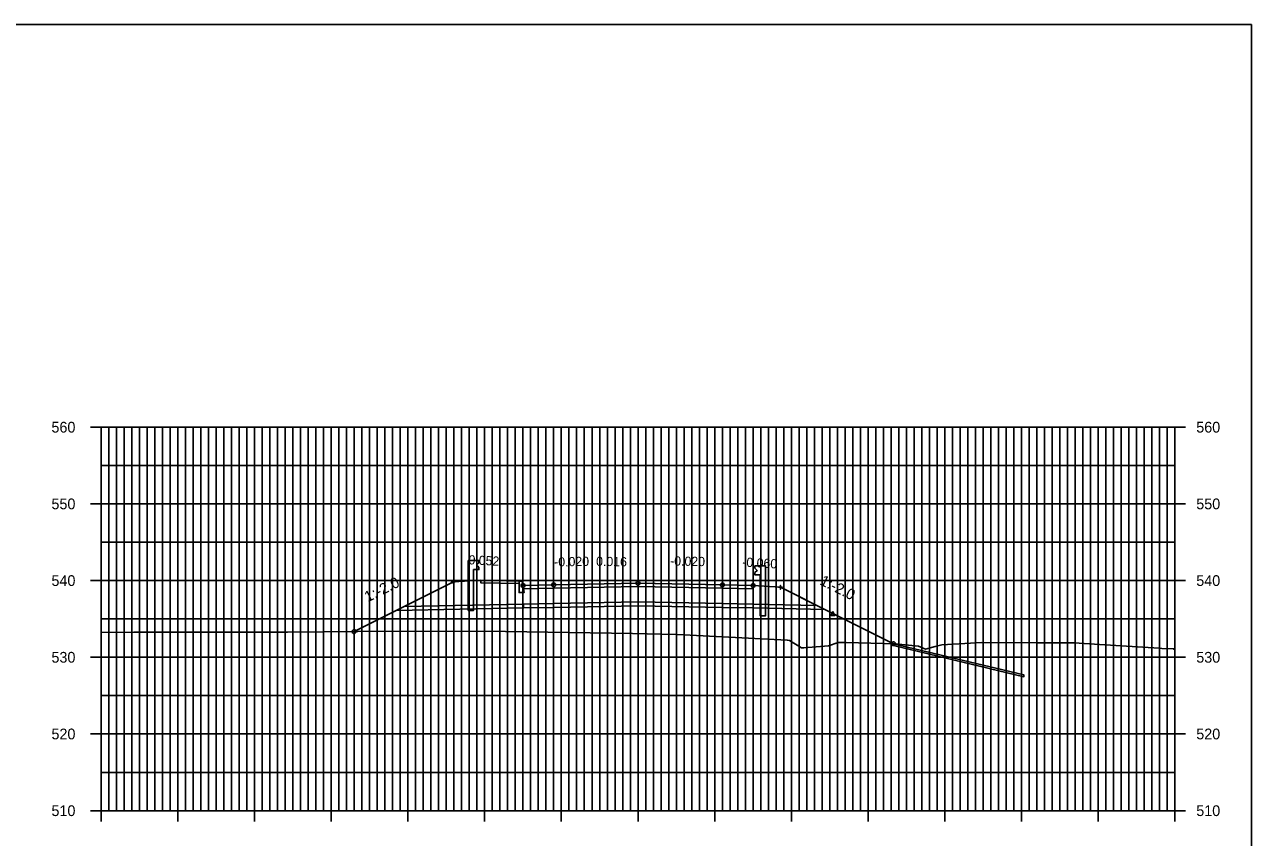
# Model space of a CAD drawing. Extents: x 1509063 to 1512863, y 401160 to 402918.
# Drawn here: x 1511622.7 to 1511782.7, y 402356.1 to 402462.1 of the extents above; entities that cross this region are included whole.
import ezdxf

# ---------------------------------------------------------------- set-up
doc = ezdxf.new("R2010")
doc.units = 0
for name, color, linetype in [('DD_P', 7, 'Continuous'), ('DDG_P', 7, 'Continuous'), ('LFILL_P', 7, 'Continuous'), ('NBL1', 7, 'Continuous'), ('PET_P', 7, 'Continuous'), ('PRC', 7, 'Continuous'), ('PSP_P', 7, 'Continuous'), ('RBS_P', 7, 'Continuous'), ('RCC_P', 7, 'Continuous'), ('RGR_P', 7, 'Continuous'), ('XAX_P', 7, 'Continuous'), ('XAXTIC_P', 7, 'Continuous'), ('XAXTXT_P_T', 7, 'Continuous'), ('XGL_P', 7, 'Continuous'), ('XSL1_P', 7, 'Continuous'), ('XSL1_P_T', 7, 'Continuous'), ('XSL2_P', 7, 'Continuous'), ('XSL3_P', 7, 'Continuous'), ('XSLOG', 7, 'Continuous')]:
    doc.layers.add(name, color=color, linetype=linetype)

msp = doc.modelspace()

# ---------------------------------------------------------------- linework, layer by layer
at = {"layer": 'DD_P'}
msp.add_lwpolyline([(1511728.15, 402385.55), (1511728.4, 402385.05), (1511727.9, 402385.05)], close=True, dxfattribs=at)
at = {"layer": 'DDG_P'}
msp.add_lwpolyline([(1511736.04, 402381.35), (1511753.05, 402377.29), (1511753.05, 402377.04), (1511736.04, 402381.1)], close=True, dxfattribs=at)
at = {"layer": 'LFILL_P'}
for points in [[(1511665.7, 402382.93), (1511678.65, 402389.41), (1511682.23, 402389.62)], [(1511717.73, 402388.93), (1511721.31, 402388.71), (1511728.15, 402385.3), (1511736.04, 402381.35)]]:
    msp.add_lwpolyline(points, dxfattribs=at)
for centre in [(1511665.7, 402382.93), (1511736.04, 402381.35)]:
    msp.add_circle(centre, 0.25, dxfattribs=at)
at = {"layer": 'NBL1'}
msp.add_lwpolyline([(1511782.73, 402252.08), (1511462.73, 402252.08), (1511462.73, 402462.08), (1511782.73, 402462.08)], close=True, dxfattribs=at)
at = {"layer": 'PET_P'}
for centre in [(1511691.73, 402389.01), (1511713.73, 402389.01)]:
    msp.add_circle(centre, 0.25, dxfattribs=at)
at = {"layer": 'PRC'}
msp.add_circle((1511702.73, 402389.23), 0.25, dxfattribs=at)
at = {"layer": 'PSP_P'}
for centre in [(1511687.73, 402388.93), (1511717.73, 402388.93)]:
    msp.add_circle(centre, 0.25, dxfattribs=at)
at = {"layer": 'RBS_P'}
for points in [[(1511687.8, 402388.51), (1511691.73, 402388.59), (1511702.73, 402388.81), (1511702.73, 402386.81), (1511691.73, 402386.59), (1511687.8, 402386.51), (1511672.24, 402386.2), (1511678.65, 402389.41), (1511682.23, 402389.62), (1511682.23, 402389.29), (1511687.23, 402389.19), (1511687.23, 402388.02), (1511687.88, 402388.02)], [(1511702.73, 402388.81), (1511702.73, 402386.81), (1511713.73, 402386.59), (1511717.73, 402386.51), (1511726.05, 402386.35), (1511721.31, 402388.71), (1511717.73, 402388.93), (1511717.73, 402388.51), (1511713.73, 402388.59)]]:
    msp.add_lwpolyline(points, close=True, dxfattribs=at)
for points in [[(1511678.65, 402389.41), (1511678.65, 402389.66), (1511678.65, 402389.41), (1511678.4, 402389.41), (1511678.65, 402389.41), (1511678.65, 402389.16), (1511678.65, 402389.41), (1511678.9, 402389.41)], [(1511721.31, 402388.71), (1511721.31, 402388.96), (1511721.31, 402388.71), (1511721.06, 402388.71), (1511721.31, 402388.71), (1511721.31, 402388.46), (1511721.31, 402388.71), (1511721.56, 402388.71)]]:
    msp.add_lwpolyline(points, dxfattribs=at)
at = {"layer": 'RCC_P'}
msp.add_lwpolyline([(1511687.73, 402388.93), (1511687.63, 402389.51), (1511687.23, 402389.52), (1511687.23, 402388.02), (1511687.88, 402388.02)], close=True, dxfattribs=at)
at = {"layer": 'RGR_P'}
for points in [[(1511681.29, 402391.02), (1511681.98, 402391.02), (1511681.98, 402391.32), (1511681.68, 402391.6), (1511681.98, 402391.89), (1511681.98, 402392.19), (1511680.6, 402392.19), (1511680.6, 402385.69), (1511681.29, 402385.69)], [(1511718.66, 402390.33), (1511717.98, 402390.33), (1511717.98, 402390.63), (1511718.28, 402390.91), (1511717.98, 402391.2), (1511717.98, 402391.5), (1511719.36, 402391.5), (1511719.36, 402385), (1511718.66, 402385)]]:
    msp.add_lwpolyline(points, close=True, dxfattribs=at)
at = {"layer": 'XAX_P'}
for p, q in [((1511632.73, 402359.58), (1511632.73, 402409.58)), ((1511702.73, 402359.58), (1511702.73, 402409.58)), ((1511772.73, 402359.58), (1511772.73, 402409.58)), ((1511632.73, 402359.58), (1511772.73, 402359.58))]:
    msp.add_line(p, q, dxfattribs=at)
at = {"layer": 'XAXTIC_P'}
for p, q in [((1511631.33, 402409.58), (1511634.13, 402409.58)), ((1511701.33, 402409.58), (1511704.13, 402409.58)), ((1511774.13, 402409.58), (1511771.33, 402409.58)), ((1511631.33, 402399.58), (1511634.13, 402399.58)), ((1511701.33, 402399.58), (1511704.13, 402399.58)), ((1511774.13, 402399.58), (1511771.33, 402399.58)), ((1511631.33, 402389.58), (1511634.13, 402389.58)), ((1511701.33, 402389.58), (1511704.13, 402389.58)), ((1511774.13, 402389.58), (1511771.33, 402389.58)), ((1511631.33, 402379.58), (1511634.13, 402379.58)), ((1511701.33, 402379.58), (1511704.13, 402379.58)), ((1511774.13, 402379.58), (1511771.33, 402379.58)), ((1511631.33, 402369.58), (1511634.13, 402369.58)), ((1511701.33, 402369.58), (1511704.13, 402369.58)), ((1511774.13, 402369.58), (1511771.33, 402369.58)), ((1511632.73, 402358.18), (1511632.73, 402360.98)), ((1511642.73, 402358.18), (1511642.73, 402360.98)), ((1511652.73, 402358.18), (1511652.73, 402360.98)), ((1511662.73, 402358.18), (1511662.73, 402360.98)), ((1511672.73, 402358.18), (1511672.73, 402360.98)), ((1511682.73, 402358.18), (1511682.73, 402360.98)), ((1511692.73, 402358.18), (1511692.73, 402360.98)), ((1511702.73, 402358.18), (1511702.73, 402360.98)), ((1511712.73, 402358.18), (1511712.73, 402360.98)), ((1511722.73, 402358.18), (1511722.73, 402360.98)), ((1511732.73, 402358.18), (1511732.73, 402360.98)), ((1511742.73, 402358.18), (1511742.73, 402360.98)), ((1511752.73, 402358.18), (1511752.73, 402360.98)), ((1511762.73, 402358.18), (1511762.73, 402360.98)), ((1511772.73, 402358.18), (1511772.73, 402360.98)), ((1511631.33, 402359.58), (1511634.13, 402359.58)), ((1511701.33, 402359.58), (1511704.13, 402359.58)), ((1511774.13, 402359.58), (1511771.33, 402359.58))]:
    msp.add_line(p, q, dxfattribs=at)
at = {"layer": 'XGL_P'}
for p, q in [((1511632.73, 402409.58), (1511772.73, 402409.58)), ((1511632.73, 402359.58), (1511632.73, 402409.58)), ((1511633.73, 402359.58), (1511633.73, 402409.58)), ((1511634.73, 402359.58), (1511634.73, 402409.58)), ((1511635.73, 402359.58), (1511635.73, 402409.58)), ((1511636.73, 402359.58), (1511636.73, 402409.58)), ((1511637.73, 402359.58), (1511637.73, 402409.58)), ((1511638.73, 402359.58), (1511638.73, 402409.58)), ((1511639.73, 402359.58), (1511639.73, 402409.58)), ((1511640.73, 402359.58), (1511640.73, 402409.58)), ((1511641.73, 402359.58), (1511641.73, 402409.58)), ((1511642.73, 402359.58), (1511642.73, 402409.58)), ((1511643.73, 402359.58), (1511643.73, 402409.58)), ((1511644.73, 402359.58), (1511644.73, 402409.58)), ((1511645.73, 402359.58), (1511645.73, 402409.58)), ((1511646.73, 402359.58), (1511646.73, 402409.58)), ((1511647.73, 402359.58), (1511647.73, 402409.58)), ((1511648.73, 402359.58), (1511648.73, 402409.58)), ((1511649.73, 402359.58), (1511649.73, 402409.58)), ((1511650.73, 402359.58), (1511650.73, 402409.58)), ((1511651.73, 402359.58), (1511651.73, 402409.58)), ((1511652.73, 402359.58), (1511652.73, 402409.58)), ((1511653.73, 402359.58), (1511653.73, 402409.58)), ((1511654.73, 402359.58), (1511654.73, 402409.58)), ((1511655.73, 402359.58), (1511655.73, 402409.58)), ((1511656.73, 402359.58), (1511656.73, 402409.58)), ((1511657.73, 402359.58), (1511657.73, 402409.58)), ((1511658.73, 402359.58), (1511658.73, 402409.58)), ((1511659.73, 402359.58), (1511659.73, 402409.58)), ((1511660.73, 402359.58), (1511660.73, 402409.58)), ((1511661.73, 402359.58), (1511661.73, 402409.58)), ((1511662.73, 402359.58), (1511662.73, 402409.58)), ((1511663.73, 402359.58), (1511663.73, 402409.58)), ((1511664.73, 402359.58), (1511664.73, 402409.58)), ((1511665.73, 402359.58), (1511665.73, 402409.58)), ((1511666.73, 402359.58), (1511666.73, 402409.58)), ((1511667.73, 402359.58), (1511667.73, 402409.58)), ((1511668.73, 402359.58), (1511668.73, 402409.58)), ((1511669.73, 402359.58), (1511669.73, 402409.58)), ((1511670.73, 402359.58), (1511670.73, 402409.58)), ((1511671.73, 402359.58), (1511671.73, 402409.58)), ((1511672.73, 402359.58), (1511672.73, 402409.58)), ((1511673.73, 402359.58), (1511673.73, 402409.58)), ((1511674.73, 402359.58), (1511674.73, 402409.58)), ((1511675.73, 402359.58), (1511675.73, 402409.58)), ((1511676.73, 402359.58), (1511676.73, 402409.58)), ((1511677.73, 402359.58), (1511677.73, 402409.58)), ((1511678.73, 402359.58), (1511678.73, 402409.58)), ((1511679.73, 402359.58), (1511679.73, 402409.58)), ((1511680.73, 402359.58), (1511680.73, 402409.58)), ((1511681.73, 402359.58), (1511681.73, 402409.58)), ((1511682.73, 402359.58), (1511682.73, 402409.58)), ((1511683.73, 402359.58), (1511683.73, 402409.58)), ((1511684.73, 402359.58), (1511684.73, 402409.58)), ((1511685.73, 402359.58), (1511685.73, 402409.58)), ((1511686.73, 402359.58), (1511686.73, 402409.58)), ((1511687.73, 402359.58), (1511687.73, 402409.58)), ((1511688.73, 402359.58), (1511688.73, 402409.58)), ((1511689.73, 402359.58), (1511689.73, 402409.58)), ((1511690.73, 402359.58), (1511690.73, 402409.58)), ((1511691.73, 402359.58), (1511691.73, 402409.58)), ((1511692.73, 402359.58), (1511692.73, 402409.58)), ((1511693.73, 402359.58), (1511693.73, 402409.58)), ((1511694.73, 402359.58), (1511694.73, 402409.58)), ((1511695.73, 402359.58), (1511695.73, 402409.58)), ((1511696.73, 402359.58), (1511696.73, 402409.58)), ((1511697.73, 402359.58), (1511697.73, 402409.58)), ((1511698.73, 402359.58), (1511698.73, 402409.58)), ((1511699.73, 402359.58), (1511699.73, 402409.58)), ((1511700.73, 402359.58), (1511700.73, 402409.58)), ((1511701.73, 402359.58), (1511701.73, 402409.58)), ((1511702.73, 402359.58), (1511702.73, 402409.58)), ((1511703.73, 402359.58), (1511703.73, 402409.58)), ((1511704.73, 402359.58), (1511704.73, 402409.58)), ((1511705.73, 402359.58), (1511705.73, 402409.58)), ((1511706.73, 402359.58), (1511706.73, 402409.58)), ((1511707.73, 402359.58), (1511707.73, 402409.58)), ((1511708.73, 402359.58), (1511708.73, 402409.58)), ((1511709.73, 402359.58), (1511709.73, 402409.58)), ((1511710.73, 402359.58), (1511710.73, 402409.58)), ((1511711.73, 402359.58), (1511711.73, 402409.58)), ((1511712.73, 402359.58), (1511712.73, 402409.58)), ((1511713.73, 402359.58), (1511713.73, 402409.58)), ((1511714.73, 402359.58), (1511714.73, 402409.58)), ((1511715.73, 402359.58), (1511715.73, 402409.58)), ((1511716.73, 402359.58), (1511716.73, 402409.58)), ((1511717.73, 402359.58), (1511717.73, 402409.58)), ((1511718.73, 402359.58), (1511718.73, 402409.58)), ((1511719.73, 402359.58), (1511719.73, 402409.58)), ((1511720.73, 402359.58), (1511720.73, 402409.58)), ((1511721.73, 402359.58), (1511721.73, 402409.58)), ((1511722.73, 402359.58), (1511722.73, 402409.58)), ((1511723.73, 402359.58), (1511723.73, 402409.58)), ((1511724.73, 402359.58), (1511724.73, 402409.58)), ((1511725.73, 402359.58), (1511725.73, 402409.58)), ((1511726.73, 402359.58), (1511726.73, 402409.58)), ((1511727.73, 402359.58), (1511727.73, 402409.58)), ((1511728.73, 402359.58), (1511728.73, 402409.58)), ((1511729.73, 402359.58), (1511729.73, 402409.58)), ((1511730.73, 402359.58), (1511730.73, 402409.58)), ((1511731.73, 402359.58), (1511731.73, 402409.58)), ((1511732.73, 402359.58), (1511732.73, 402409.58)), ((1511733.73, 402359.58), (1511733.73, 402409.58)), ((1511734.73, 402359.58), (1511734.73, 402409.58)), ((1511735.73, 402359.58), (1511735.73, 402409.58)), ((1511736.73, 402359.58), (1511736.73, 402409.58)), ((1511737.73, 402359.58), (1511737.73, 402409.58)), ((1511738.73, 402359.58), (1511738.73, 402409.58)), ((1511739.73, 402359.58), (1511739.73, 402409.58)), ((1511740.73, 402359.58), (1511740.73, 402409.58)), ((1511741.73, 402359.58), (1511741.73, 402409.58)), ((1511742.73, 402359.58), (1511742.73, 402409.58)), ((1511743.73, 402359.58), (1511743.73, 402409.58)), ((1511744.73, 402359.58), (1511744.73, 402409.58)), ((1511745.73, 402359.58), (1511745.73, 402409.58)), ((1511746.73, 402359.58), (1511746.73, 402409.58)), ((1511747.73, 402359.58), (1511747.73, 402409.58)), ((1511748.73, 402359.58), (1511748.73, 402409.58)), ((1511749.73, 402359.58), (1511749.73, 402409.58)), ((1511750.73, 402359.58), (1511750.73, 402409.58)), ((1511751.73, 402359.58), (1511751.73, 402409.58)), ((1511752.73, 402359.58), (1511752.73, 402409.58)), ((1511753.73, 402359.58), (1511753.73, 402409.58)), ((1511754.73, 402359.58), (1511754.73, 402409.58)), ((1511755.73, 402359.58), (1511755.73, 402409.58)), ((1511756.73, 402359.58), (1511756.73, 402409.58)), ((1511757.73, 402359.58), (1511757.73, 402409.58)), ((1511758.73, 402359.58), (1511758.73, 402409.58)), ((1511759.73, 402359.58), (1511759.73, 402409.58)), ((1511760.73, 402359.58), (1511760.73, 402409.58)), ((1511761.73, 402359.58), (1511761.73, 402409.58)), ((1511762.73, 402359.58), (1511762.73, 402409.58)), ((1511763.73, 402359.58), (1511763.73, 402409.58)), ((1511764.73, 402359.58), (1511764.73, 402409.58)), ((1511765.73, 402359.58), (1511765.73, 402409.58)), ((1511766.73, 402359.58), (1511766.73, 402409.58)), ((1511767.73, 402359.58), (1511767.73, 402409.58)), ((1511768.73, 402359.58), (1511768.73, 402409.58)), ((1511769.73, 402359.58), (1511769.73, 402409.58)), ((1511770.73, 402359.58), (1511770.73, 402409.58)), ((1511771.73, 402359.58), (1511771.73, 402409.58)), ((1511772.73, 402359.58), (1511772.73, 402409.58)), ((1511632.73, 402404.58), (1511772.73, 402404.58)), ((1511632.73, 402399.58), (1511772.73, 402399.58)), ((1511632.73, 402394.58), (1511772.73, 402394.58)), ((1511632.73, 402389.58), (1511772.73, 402389.58)), ((1511632.73, 402384.58), (1511772.73, 402384.58)), ((1511632.73, 402379.58), (1511772.73, 402379.58)), ((1511632.73, 402374.58), (1511772.73, 402374.58)), ((1511632.73, 402369.58), (1511772.73, 402369.58)), ((1511632.73, 402364.58), (1511772.73, 402364.58)), ((1511632.73, 402359.58), (1511772.73, 402359.58))]:
    msp.add_line(p, q, dxfattribs=at)
at = {"layer": 'XSL1_P'}
msp.add_lwpolyline([(1511665.7, 402382.93), (1511672.24, 402386.2), (1511678.65, 402389.41), (1511682.23, 402389.62), (1511687.23, 402389.52), (1511687.63, 402389.51), (1511687.73, 402388.93), (1511691.73, 402389.01), (1511702.73, 402389.23), (1511713.73, 402389.01), (1511717.73, 402388.93), (1511721.31, 402388.71), (1511726.05, 402386.35), (1511727.09, 402385.83), (1511728.15, 402385.3), (1511736.04, 402381.35), (1511753.05, 402377.3)], dxfattribs=at)
msp.add_lwpolyline([(1511687.23, 402389.52), (1511682.23, 402389.62), (1511682.23, 402389.29), (1511687.23, 402389.19)], close=True, dxfattribs=at)
at = {"layer": 'XSL2_P'}
for points in [[(1511687.8, 402386.51), (1511672.24, 402386.2), (1511671.2, 402385.68), (1511687.8, 402386.01)], [(1511713.73, 402386.09), (1511702.73, 402386.31), (1511691.73, 402386.09), (1511687.8, 402386.01), (1511687.8, 402386.51), (1511691.73, 402386.59), (1511702.73, 402386.81), (1511713.73, 402386.59), (1511717.73, 402386.51), (1511717.73, 402386.01)], [(1511717.73, 402386.51), (1511726.05, 402386.35), (1511727.09, 402385.83), (1511717.73, 402386.01)]]:
    msp.add_lwpolyline(points, close=True, dxfattribs=at)
for points in [[(1511672.24, 402386.2), (1511687.8, 402386.51)], [(1511717.73, 402386.51), (1511726.05, 402386.35)]]:
    msp.add_lwpolyline(points, dxfattribs=at)
at = {"layer": 'XSL3_P'}
msp.add_lwpolyline([(1511691.73, 402388.59), (1511687.8, 402388.51), (1511687.73, 402388.93), (1511691.73, 402389.01), (1511702.73, 402389.23), (1511713.73, 402389.01), (1511717.73, 402388.93), (1511717.73, 402388.51), (1511713.73, 402388.59), (1511702.73, 402388.81)], close=True, dxfattribs=at)
at = {"layer": 'XSLOG'}
msp.add_lwpolyline([(1511632.73, 402382.82), (1511636.98, 402382.85), (1511657.03, 402382.87), (1511666.19, 402382.93), (1511682.69, 402382.99), (1511701.99, 402382.69), (1511707.73, 402382.56), (1511709.51, 402382.47), (1511722.2, 402381.83), (1511722.47, 402381.77), (1511724.04, 402380.83), (1511724.34, 402380.81), (1511727.07, 402381.05), (1511727.55, 402381.09), (1511728.82, 402381.49), (1511729.86, 402381.49), (1511736.3, 402381.35), (1511736.7, 402381.3), (1511739.29, 402381.05), (1511740.22, 402380.62), (1511741.5, 402380.98), (1511742.33, 402381.19), (1511746.84, 402381.47), (1511747.54, 402381.49), (1511754.72, 402381.47), (1511759.59, 402381.46), (1511762.92, 402381.25), (1511770.68, 402380.76), (1511771.05, 402380.73), (1511772.56, 402380.67), (1511772.73, 402380.57)], dxfattribs=at)

# ---------------------------------------------------------------- texts
at = {"layer": 'XAXTXT_P_T'}
for s, p in [('560', (1511626.24, 402408.88)), ('560', (1511775.53, 402408.88)), ('550', (1511626.24, 402398.88)), ('550', (1511775.53, 402398.88)), ('540', (1511626.24, 402388.88)), ('540', (1511775.53, 402388.88)), ('530', (1511626.24, 402378.88)), ('530', (1511775.53, 402378.88)), ('520', (1511626.24, 402368.88)), ('520', (1511775.53, 402368.88)), ('510', (1511626.24, 402358.88)), ('510', (1511775.53, 402358.88))]:
    msp.add_text(s, height=1.4, dxfattribs=at).set_placement(p)
at = {"layer": 'XSL1_P_T'}
for s, height, rotation, p in [('0.052', 1.2, 356.9978, (1511680.6, 402391.71)), ('-0.020', 1.2, 1.1458, (1511691.81, 402391.41)), ('0.016', 1.2, 359.0716, (1511697.26, 402391.5)), ('0.016', 1.2, 359.0716, (1511697.26, 402391.5)), ('-0.020', 1.2, 358.8542, (1511706.91, 402391.55)), ('-0.060', 1.2, 356.5664, (1511716.3, 402391.42)), ('1:-2.0', 1.4, 26.5651, (1511667.49, 402386.74)), ('1:-2.0', 1.4, 26.5651, (1511667.49, 402386.74)), ('1:-2.0', 1.4, 26.5651, (1511667.49, 402386.74)), ('1:-2.0', 1.4, 333.4349, (1511726.32, 402389.12)), ('1:-2.0', 1.4, 333.4349, (1511726.32, 402389.12)), ('1:-2.0', 1.4, 333.4349, (1511726.32, 402389.12))]:
    msp.add_text(s, height=height, rotation=rotation, dxfattribs=at).set_placement(p)

doc.saveas('drawing.dxf')
